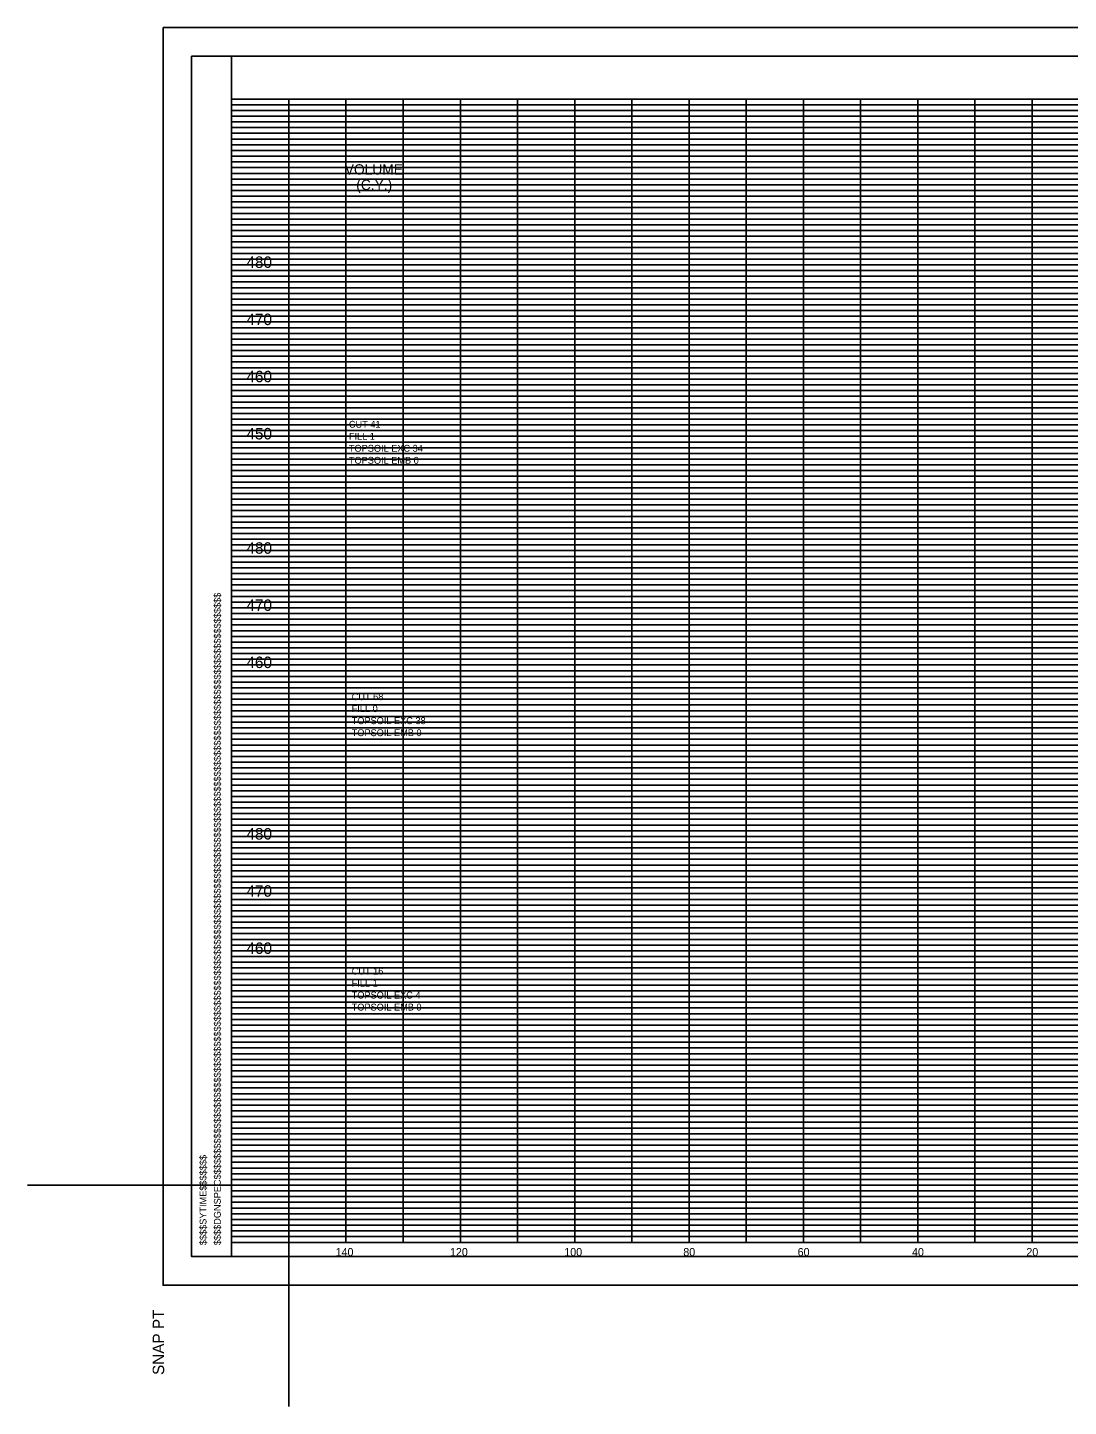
# Model space of a CAD drawing. Extents: x 37 to 1710, y 707 to 2305.
# Drawn here: x 964.3 to 1146.3, y 971.3 to 1212.5 of the extents above; entities that cross this region are included whole.
import ezdxf

# ---------------------------------------------------------------- set-up
doc = ezdxf.new("R2010")
doc.units = 0
for name, color, linetype in [('DESIGN - SCRATCH - User 1', 7, 'Continuous'), ('DESIGN - SHEET - Corner Text', 7, 'Continuous'), ('DESIGN - SHEET - Light Grid', 7, 'Continuous'), ('DESIGN - SHEET - Linework', 7, 'Continuous'), ('DESIGN - SHEET - Plot Shape', 7, 'Continuous'), ('DESIGN - TYPICAL - Text', 7, 'Continuous')]:
    doc.layers.add(name, color=color, linetype=linetype)

msp = doc.modelspace()

# ---------------------------------------------------------------- linework, layer by layer
at = {"layer": 'DESIGN - SCRATCH - User 1'}
for p, q in [((1010, 1010), (964.31, 1010)), ((1010, 1010), (1010, 971.3)), ((1000, 1000), (1000, 1000))]:
    msp.add_line(p, q, dxfattribs=at)
at = {"layer": 'DESIGN - SHEET - Light Grid'}
for p, q in [((1000, 1199), (1280, 1199)), ((1000, 1198), (1280, 1198)), ((1000, 1197), (1320, 1197)), ((1000, 1196), (1320, 1196)), ((1000, 1195), (1320, 1195)), ((1000, 1194), (1320, 1194)), ((1000, 1193), (1320, 1193)), ((1000, 1192), (1320, 1192)), ((1000, 1191), (1320, 1191)), ((1000, 1189), (1320, 1189)), ((1000, 1188), (1320, 1188)), ((1000, 1187), (1320, 1187)), ((1000, 1186), (1320, 1186)), ((1000, 1185), (1320, 1185)), ((1000, 1184), (1320, 1184)), ((1000, 1183), (1320, 1183)), ((1000, 1182), (1320, 1182)), ((1000, 1181), (1320, 1181)), ((1000, 1179), (1320, 1179)), ((1000, 1178), (1320, 1178)), ((1000, 1177), (1320, 1177)), ((1000, 1176), (1320, 1176)), ((1000, 1175), (1320, 1175)), ((1000, 1174), (1320, 1174)), ((1000, 1173), (1320, 1173)), ((1000, 1172), (1320, 1172)), ((1000, 1171), (1320, 1171)), ((1000, 1169), (1320, 1169)), ((1000, 1168), (1320, 1168)), ((1000, 1167), (1320, 1167)), ((1000, 1166), (1320, 1166)), ((1000, 1165), (1320, 1165)), ((1000, 1164), (1320, 1164)), ((1000, 1163), (1320, 1163)), ((1000, 1162), (1320, 1162)), ((1000, 1161), (1320, 1161)), ((1000, 1159), (1320, 1159)), ((1000, 1158), (1320, 1158)), ((1000, 1157), (1320, 1157)), ((1000, 1156), (1320, 1156)), ((1000, 1155), (1320, 1155)), ((1000, 1154), (1320, 1154)), ((1000, 1153), (1320, 1153)), ((1000, 1152), (1320, 1152)), ((1000, 1151), (1320, 1151)), ((1000, 1149), (1320, 1149)), ((1000, 1148), (1320, 1148)), ((1000, 1147), (1320, 1147)), ((1000, 1146), (1320, 1146)), ((1000, 1145), (1320, 1145)), ((1000, 1144), (1320, 1144)), ((1000, 1143), (1320, 1143)), ((1000, 1142), (1320, 1142)), ((1000, 1141), (1320, 1141)), ((1000, 1139), (1320, 1139)), ((1000, 1138), (1320, 1138)), ((1000, 1137), (1320, 1137)), ((1000, 1136), (1320, 1136)), ((1000, 1135), (1320, 1135)), ((1000, 1134), (1320, 1134)), ((1000, 1133), (1320, 1133)), ((1000, 1132), (1320, 1132)), ((1000, 1131), (1320, 1131)), ((1000, 1129), (1320, 1129)), ((1000, 1128), (1320, 1128)), ((1000, 1127), (1320, 1127)), ((1000, 1126), (1320, 1126)), ((1000, 1125), (1320, 1125)), ((1000, 1124), (1320, 1124)), ((1000, 1123), (1320, 1123)), ((1000, 1122), (1320, 1122)), ((1000, 1121), (1320, 1121)), ((1000, 1119), (1320, 1119)), ((1000, 1118), (1320, 1118)), ((1000, 1117), (1320, 1117)), ((1000, 1116), (1320, 1116)), ((1000, 1115), (1320, 1115)), ((1000, 1114), (1320, 1114)), ((1000, 1113), (1320, 1113)), ((1000, 1112), (1320, 1112)), ((1000, 1111), (1320, 1111)), ((1000, 1109), (1320, 1109)), ((1000, 1108), (1320, 1108)), ((1000, 1107), (1320, 1107)), ((1000, 1106), (1320, 1106)), ((1000, 1105), (1320, 1105)), ((1000, 1104), (1320, 1104)), ((1000, 1103), (1320, 1103)), ((1000, 1102), (1320, 1102)), ((1000, 1101), (1320, 1101)), ((1000, 1099), (1320, 1099)), ((1000, 1098), (1320, 1098)), ((1000, 1097), (1320, 1097)), ((1000, 1096), (1320, 1096)), ((1000, 1095), (1320, 1095)), ((1000, 1094), (1320, 1094)), ((1000, 1093), (1320, 1093)), ((1000, 1092), (1320, 1092)), ((1000, 1091), (1320, 1091)), ((1000, 1089), (1320, 1089)), ((1000, 1088), (1320, 1088)), ((1000, 1087), (1320, 1087)), ((1000, 1086), (1320, 1086)), ((1000, 1085), (1320, 1085)), ((1000, 1084), (1320, 1084)), ((1000, 1083), (1320, 1083)), ((1000, 1082), (1320, 1082)), ((1000, 1081), (1320, 1081)), ((1000, 1079), (1320, 1079)), ((1000, 1078), (1320, 1078)), ((1000, 1077), (1320, 1077)), ((1000, 1076), (1320, 1076)), ((1000, 1075), (1320, 1075)), ((1000, 1074), (1320, 1074)), ((1000, 1073), (1320, 1073)), ((1000, 1072), (1320, 1072)), ((1000, 1071), (1320, 1071)), ((1000, 1069), (1320, 1069)), ((1000, 1068), (1320, 1068)), ((1000, 1067), (1320, 1067)), ((1000, 1066), (1320, 1066)), ((1000, 1065), (1320, 1065)), ((1000, 1064), (1320, 1064)), ((1000, 1063), (1320, 1063)), ((1000, 1062), (1320, 1062)), ((1000, 1061), (1320, 1061)), ((1000, 1059), (1320, 1059)), ((1000, 1058), (1320, 1058)), ((1000, 1057), (1320, 1057)), ((1000, 1056), (1320, 1056)), ((1000, 1055), (1320, 1055)), ((1000, 1054), (1320, 1054)), ((1000, 1053), (1320, 1053)), ((1000, 1052), (1320, 1052)), ((1000, 1051), (1320, 1051)), ((1000, 1049), (1320, 1049)), ((1000, 1048), (1320, 1048)), ((1000, 1047), (1320, 1047)), ((1000, 1046), (1320, 1046)), ((1000, 1045), (1320, 1045)), ((1000, 1044), (1320, 1044)), ((1000, 1043), (1320, 1043)), ((1000, 1042), (1320, 1042)), ((1000, 1041), (1320, 1041)), ((1000, 1039), (1320, 1039)), ((1000, 1038), (1320, 1038)), ((1000, 1037), (1320, 1037)), ((1000, 1036), (1320, 1036)), ((1000, 1035), (1320, 1035)), ((1000, 1034), (1320, 1034)), ((1000, 1033), (1320, 1033)), ((1000, 1032), (1320, 1032)), ((1000, 1031), (1320, 1031)), ((1000, 1029), (1320, 1029)), ((1000, 1028), (1320, 1028)), ((1000, 1027), (1320, 1027)), ((1000, 1026), (1320, 1026)), ((1000, 1025), (1320, 1025)), ((1000, 1024), (1320, 1024)), ((1000, 1023), (1320, 1023)), ((1000, 1022), (1320, 1022)), ((1000, 1021), (1320, 1021)), ((1000, 1019), (1320, 1019)), ((1000, 1018), (1320, 1018)), ((1000, 1017), (1320, 1017)), ((1000, 1016), (1320, 1016)), ((1000, 1015), (1320, 1015)), ((1000, 1014), (1320, 1014)), ((1000, 1013), (1320, 1013)), ((1000, 1012), (1320, 1012)), ((1000, 1011), (1320, 1011)), ((1000, 1009), (1320, 1009)), ((1000, 1008), (1320, 1008)), ((1000, 1007), (1320, 1007)), ((1000, 1006), (1320, 1006)), ((1000, 1005), (1320, 1005)), ((1000, 1004), (1320, 1004)), ((1000, 1003), (1320, 1003)), ((1000, 1002), (1320, 1002)), ((1000, 1001), (1320, 1001))]:
    msp.add_line(p, q, dxfattribs=at)
at = {"layer": 'DESIGN - SHEET - Linework'}
for p, q in [((1000, 1200), (1320, 1200)), ((1010, 1000), (1010, 1200)), ((1020, 1000), (1020, 1200)), ((1030, 1000), (1030, 1200)), ((1040, 1000), (1040, 1200)), ((1050, 1000), (1050, 1200)), ((1060, 1000), (1060, 1200)), ((1070, 1000), (1070, 1200)), ((1080, 1000), (1080, 1200)), ((1090, 1000), (1090, 1200)), ((1100, 1000), (1100, 1200)), ((1110, 1000), (1110, 1200)), ((1120, 1000), (1120, 1200)), ((1130, 1000), (1130, 1200)), ((1140, 1000), (1140, 1200)), ((1000, 1190), (1320, 1190)), ((1000, 1180), (1320, 1180)), ((1000, 1170), (1320, 1170)), ((1000, 1160), (1320, 1160)), ((1000, 1150), (1320, 1150)), ((1000, 1140), (1320, 1140)), ((1000, 1130), (1320, 1130)), ((1000, 1120), (1320, 1120)), ((1000, 1110), (1320, 1110)), ((1000, 1100), (1320, 1100)), ((1000, 1090), (1320, 1090)), ((1000, 1080), (1320, 1080)), ((1000, 1070), (1320, 1070)), ((1000, 1060), (1320, 1060)), ((1000, 1050), (1320, 1050)), ((1000, 1040), (1320, 1040)), ((1000, 1030), (1320, 1030)), ((1000, 1020), (1320, 1020)), ((1000, 1010), (1320, 1010)), ((1000, 1000), (1320, 1000))]:
    msp.add_line(p, q, dxfattribs=at)
for points in [[(988, 1212.5), (1328, 1212.5), (1328, 992.5), (988, 992.5)], [(1000, 1207.5), (1320, 1207.5), (1320, 997.5), (1000, 997.5)]]:
    msp.add_lwpolyline(points, close=True, dxfattribs=at)
at = {"layer": 'DESIGN - SHEET - Plot Shape'}
msp.add_lwpolyline([(993, 1207.5), (1323, 1207.5), (1323, 997.5), (993, 997.5)], close=True, dxfattribs=at)

# ---------------------------------------------------------------- texts
at = {"layer": 'DESIGN - SHEET - Corner Text'}
for s, height, p in [('$$$$DGNSPEC$$$$$$$$$$$$$$$$$$$$$$$$$$$$$$$$$$$$$$$$$$$$$$$$$$$$$$$$$$$$$$$$$$$$$$$$$$$$$$$$$$$$$$$$$$$$$$$$$$$$$$$$$$$$$$$$$$$', 1.2, (998.1, 999.5)), ('$$$$SYTIME$$$$$$$', 1.2, (995.6, 999.5)), ('SNAP PT  ', 2, (988.2, 976.8))]:
    msp.add_text(s, height=height, rotation=90, dxfattribs=at).set_placement(p)
at = {"layer": 'DESIGN - TYPICAL - Text'}
for s, height, p in [('VOLUME', 1.8, (1019.79, 1186.79)), ('   (C.Y.)', 1.8, (1019.79, 1184.09)), ('     480     ', 2, (998.88, 1170.46)), ('     470     ', 2, (998.88, 1160.46)), ('     460     ', 2, (998.88, 1150.46)), ('CUT 41', 1.2, (1020.51, 1142.5)), ('     450     ', 2, (998.88, 1140.46)), ('FILL 1', 1.2, (1020.51, 1140.4)), ('TOPSOIL EXC 34', 1.2, (1020.51, 1138.3)), ('TOPSOIL EMB 0', 1.2, (1020.51, 1136.2)), ('     480     ', 2, (998.88, 1120.46)), ('     470     ', 2, (998.88, 1110.46)), ('     460     ', 2, (998.88, 1100.46)), ('CUT 68', 1.2, (1021, 1094.85)), ('FILL 0', 1.2, (1021, 1092.75)), ('TOPSOIL EXC 38', 1.2, (1021, 1090.65)), ('TOPSOIL EMB 0', 1.2, (1021, 1088.55)), ('     480     ', 2, (998.88, 1070.46)), ('     470     ', 2, (998.88, 1060.46)), ('     460     ', 2, (998.88, 1050.46)), ('CUT 16', 1.2, (1021, 1046.85)), ('FILL 1', 1.2, (1021, 1044.75)), ('TOPSOIL EXC 4', 1.2, (1021, 1042.65)), ('TOPSOIL EMB 0', 1.2, (1021, 1040.55)), ('     140     ', 1.4, (1015.58, 997.6)), ('     120     ', 1.4, (1035.58, 997.6)), ('     100     ', 1.4, (1055.58, 997.6)), ('     80     ', 1.4, (1076.39, 997.6)), ('     60     ', 1.4, (1096.39, 997.6)), ('     40     ', 1.4, (1116.39, 997.6)), ('     20     ', 1.4, (1136.39, 997.6))]:
    msp.add_text(s, height=height, dxfattribs=at).set_placement(p)

doc.saveas('drawing.dxf')
